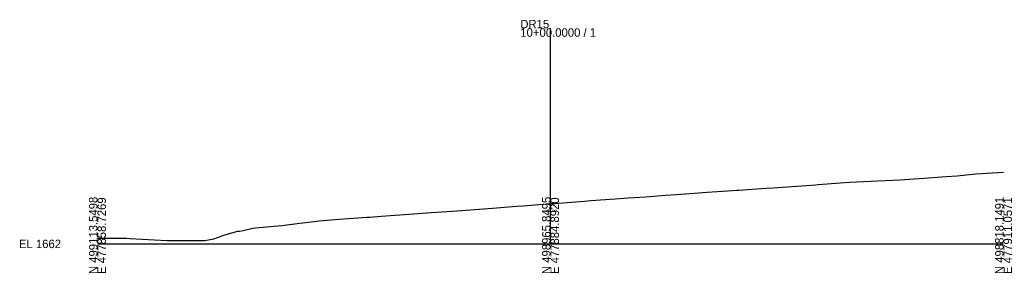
# Model space of a CAD drawing. Extents: x -26 to 303, y -10 to 4126.
# Drawn here: x -25.7 to 302.8, y -9.7 to 74.2 of the extents above; entities that cross this region are included whole.
import ezdxf

# ---------------------------------------------------------------- set-up
doc = ezdxf.new("R2010")
doc.units = 0
for name, color, linetype in [('Exist Cross Section Cell', 7, 'Continuous'), ('Exist XS Center Line Elevation Label', 7, 'Continuous'), ('Exist XS Ground Line', 7, 'Continuous')]:
    doc.layers.add(name, color=color, linetype=linetype)

msp = doc.modelspace()

# ---------------------------------------------------------------- linework, layer by layer
at = {"layer": 'Exist Cross Section Cell'}
for p, q in [((150, 0), (150, 71.38)), ((0, 0), (150, 0)), ((150, 0), (300, 0))]:
    msp.add_line(p, q, dxfattribs=at)
at = {"layer": 'Exist XS Ground Line'}
msp.add_lwpolyline([(0, 1.89), (0.38, 1.89), (9.64, 1.84), (10.69, 1.74), (22.96, 1.17), (25.55, 1.16), (35.56, 1.14), (38.57, 1.63), (42.12, 2.98), (46.49, 4.26), (47.05, 4.26), (48.25, 4.48), (51.44, 5.2), (52.37, 5.26), (61.1, 6.14), (66.95, 6.86), (69.86, 7.19), (73.46, 7.66), (79.99, 8.13), (89.33, 8.82), (90.15, 8.88), (93.92, 9.16), (100.13, 9.65), (101.68, 9.75), (110.46, 10.34), (114.02, 10.65), (120.62, 11.06), (126.37, 11.51), (130.78, 11.84), (138.71, 12.45), (140.93, 12.63), (150, 13.32), (151.26, 13.41), (161.25, 14.16), (163.4, 14.33), (171.41, 14.91), (175.75, 15.21), (181.57, 15.59), (188.09, 16.09), (191.72, 16.32), (200.43, 16.99), (201.88, 17.09), (208.6, 17.61), (211.73, 17.82), (212.23, 17.84), (221.3, 18.4), (223.68, 18.52), (237.85, 19.56), (238.66, 19.62), (248.93, 20.41), (265.6, 21.16), (273.59, 21.73), (279.5, 22.23), (281.03, 22.32), (284.59, 22.57), (290.77, 23.19), (294.34, 23.42), (300, 23.79)], dxfattribs=at)

# ---------------------------------------------------------------- texts
at = {"layer": 'Exist Cross Section Cell'}
for s, p in [('DR15', (140, 71.38)), ('10+00.0000 / 1', (140, 68.58)), ('EL 1662', (-26, -1.4))]:
    msp.add_text(s, height=2.8, dxfattribs=at).set_placement(p)
for s, p in [('N 499113.5498', (0, -10)), ('E 477858.7269', (2.8, -10)), ('N 498965.8495', (150, -10)), ('E 477884.8920', (152.8, -10)), ('N 498818.1491', (300, -10)), ('E 477911.0571', (302.8, -10))]:
    msp.add_text(s, height=2.8, rotation=90, dxfattribs=at).set_placement(p)
at = {"layer": 'Exist XS Center Line Elevation Label'}
msp.add_text('1675.32', height=0.75, dxfattribs=at).set_placement((148.21, 10.57))

doc.saveas('drawing.dxf')
